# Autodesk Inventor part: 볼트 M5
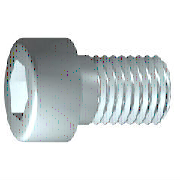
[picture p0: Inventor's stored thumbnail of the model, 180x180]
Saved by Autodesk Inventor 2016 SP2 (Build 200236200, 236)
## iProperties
IsCustomPart: 1
Created: 2012-02
Part Number: 볼트 M5
Material: 강철, 연강
Description: 6각머리 태핑 나사
Document SubType Name: Modeling
Standard: KS B 1003
Designer: mduedu
Standards Organization: KS
Language: ko-KR
Size Designation: M 5 x 16
Categories: <MemberInstance><Categories><Category DisplayName="조임쇠" InternalName="e4da775c-781d-43d5-af7c-5136215cf5a6" Mnemonic="FSTN"><Category DisplayName="볼트" InternalN
Density: 1 g/cm^3
Appearance: 강철
Author: mduedu
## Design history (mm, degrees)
sketch "스케치1"
  geometry: L1 (-1.167, 0)-(16, 0); L2 (16, 0)-(16, 2.5); L3 (16, 2.5)-(2, 2.5); L4 (2, 2.5)-(1.509, 2.5); L5 (1.509, 2.5)-(0, 2.5); L6 (0, 2.5)-(0, 4.25); L7 (0, 4.25)-(-5, 4.25); L8 (-5, 4.25)-(-5, 2.309); L9 (-5, 2.309)-(-2.5, 2.309); L10 (-2.5, 2.309)-(-1.167, 0); L11 (-9.2, 0)-(20.2, 0) reference; L12 (0, -0.85)-(0, 5.1) reference; L13 (2, 2.5)-(0, 2.5)
  constraints: 22 end point, 6 parallel, 2 collinear, 2 perpendicular, 1 horizontal, 1 point on line
  dimensions: "d1" = 14 distance from line of L3.end L2 (= GEL); "d2" = 0.49086 distance of L4.end L3.end (computed from GAL); "d3" = 5 distance between parallel lines of L8 L6 (= KOH); "d4" = 2.5 distance of L8.end L9.end (= INTI); "d5" = 60 deg angle of L10 L1; "d6" = 5 diameter of L3 L1 (= GD); "d7" = 5 diameter of L5 L1 (= BDM); "d8" = 4.6188 diameter of L9 L1 (= 1.1547 x SW); "d9" = 8.5 diameter of L7 L1 (= KOD); "d26" = 16 distance between parallel lines of L12 L2 (= NLG)
revolve "본체" sketch "스케치1" stored, may be unused: angle "d10" = 90 deg
sketch "스케치2"
  geometry: L1 (0, -5.95)-(0, 5.95) reference; L2 (-5.95, 0)-(5.95, 0) reference; L3 (2.309, 0)-(1.155, -2); L4 (1.155, -2)-(-1.155, -2); L5 (-1.155, -2)-(-2.309, 0); L6 (-2.309, 0)-(-1.155, 2); L7 (-1.155, 2)-(1.155, 2); L8 (1.155, 2)-(2.309, 0); 2 further points
  constraints: 12 end point, 1 coincident, 1 horizontal alignment, 1 point on line, 12 other
extrude "슬롯" join sketch "스케치2" stored distance "d11" = 10; taper "d12" = 0 deg
workplane "Work Plane1"
fillet "Fillet2" dims "d30" = 0.1 (= R)
body "Solid1"
fillet "모깎기1" dims "d17" = 0.5 (= RR)
feature "스레드" dims "d13" = 14 (= GEL), "d14" = 0
chamfer "모따기1" distance "d15" = 0.49076 (= -0.5 x SPD + 0.5 x GD); stored, may be unused: second distance "d16" = 0.49076 (= GUL), angle "d27" = 45 deg
other parameters: "GD" = 5 (= NND) [user parameter; used in 2 equation terms], "NLG" = 16 [user parameter; used in 1 equation term], "GEL" = 14 [user parameter; used in 2 equation terms], "KOD" = 8.5 [user parameter; used in 1 equation term], "KOH" = 5 [user parameter; used in 1 equation term], "INTI" = 2.5 [user parameter; used in 1 equation term], "GAL" = 0.49076 (= 0.61345 x PTC) [user parameter; used in 1 equation term], "GUL" = 0.49076 (= 0.61345 x PTC) [user parameter; used in 1 equation term], "BDM" = 5 (= NND) [user parameter; used in 1 equation term], "SW" = 4 [user parameter; used in 2 equation terms], "RR" = 0.5 [user parameter; used in 1 equation term], "SPD" = 4.01848 (= NND - 1.2269 x PTC) [user parameter; used in 1 equation term], "d19" = 0, "d28" = 0, "d29" = 0, "R" = 0.1 [user parameter; used in 1 equation term], "PHH" = 0.2 [user parameter], "GD1" = 4.01848 (= THREADDIA - 1.2269 x PTC) [user parameter], "THREADDIA" = 5 [user parameter; used in 1 equation term], "FAWI" = 45 deg [user parameter], "TPU" = 12.5 (computed from PTC) [user parameter], "PTC" = 0.8 [user parameter; used in 5 equation terms], "NND" = 5 [user parameter; used in 3 equation terms], "TOA" = 30 deg [user parameter], "E0" = 4.62 (= 1.155 x SW) [user parameter]
